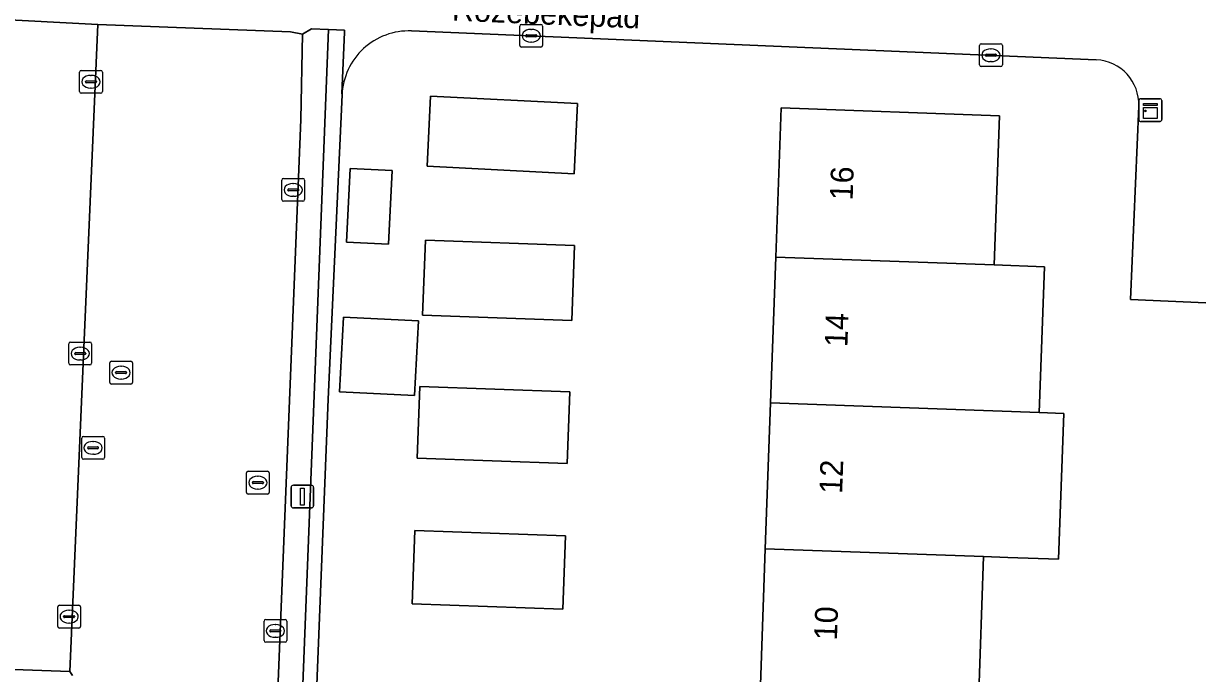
# Model space of a CAD drawing. Extents: x 160732 to 162107, y 387428 to 388479.
# Drawn here: x 161104.8 to 161156.4, y 387560.6 to 387589.1 of the extents above; entities that cross this region are included whole.
import ezdxf

# ---------------------------------------------------------------- set-up
doc = ezdxf.new("R2010")
doc.units = 0
for name, color, linetype in [('IMGEO_Brandkraan', 7, 'Continuous'), ('IMGEO_Erf', 7, 'Continuous'), ('IMGEO_Kast', 7, 'Continuous'), ('IMGEO_Kolk', 7, 'Continuous'), ('IMGEO_Lichtmast', 7, 'Continuous'), ('IMGEO_Openbare_ruimte_label', 7, 'Continuous'), ('IMGEO_Pand', 7, 'Continuous'), ('IMGEO_Pand_nummerreeks', 7, 'Continuous'), ('IMGEO_Parkeervlak_open', 7, 'Continuous'), ('IMGEO_Rijbaan_lokaal_open', 7, 'Continuous'), ('IMGEO_Rioolput', 7, 'Continuous'), ('IMGEO_Voetpad_open', 7, 'Continuous')]:
    doc.layers.add(name, color=color, linetype=linetype)

msp = doc.modelspace()

# ---------------------------------------------------------------- linework, layer by layer
at = {"layer": 'IMGEO_Brandkraan'}
for p, q in [((161114.587, 387568.537), (161114.587, 387569.389)), ((161114.662, 387569.463), (161115.514, 387569.463)), ((161115.075, 387569.243), (161115.1, 387569.243)), ((161115.588, 387569.389), (161115.588, 387568.537)), ((161114.846, 387568.957), (161114.846, 387568.969)), ((161115.284, 387568.92), (161114.886, 387568.92)), ((161114.889, 387569.006), (161115.287, 387569.006)), ((161115.098, 387568.683), (161115.073, 387568.683)), ((161115.33, 387568.969), (161115.33, 387568.957)), ((161115.514, 387568.463), (161114.662, 387568.463))]:
    msp.add_line(p, q, dxfattribs=at)
for points in [[(161114.587, 387568.537), (161114.587, 387569.389)], [(161114.662, 387569.463), (161115.514, 387569.463)], [(161115.588, 387569.389), (161115.588, 387568.537)], [(161115.514, 387568.463), (161114.662, 387568.463)]]:
    msp.add_lwpolyline(points, dxfattribs=at)
for centre, radius, start, end in [((161114.664, 387569.387), 0.0765, 91.552, 178.448), ((161114.664, 387569.387), 0.0765, 91.552, 178.448), ((161115.512, 387569.387), 0.0765, 1.552, 88.448), ((161115.512, 387569.387), 0.0765, 1.552, 88.448), ((161114.664, 387568.539), 0.0765, 181.552, 268.448), ((161114.664, 387568.539), 0.0765, 181.552, 268.448), ((161114.886, 387568.966), 0.0403, 85.8775, 175.7526), ((161114.883, 387568.956), 0.0366, 178.938, 274.7102), ((161115.287, 387568.963), 0.043, 264.8664, 352.4533), ((161115.291, 387568.968), 0.0386, 1.7309, 96.639), ((161115.512, 387568.539), 0.0765, 271.552, 358.448), ((161115.512, 387568.539), 0.0765, 271.552, 358.448)]:
    msp.add_arc(centre, radius, start, end, dxfattribs=at)
for centre, major_axis, ratio, start_param, end_param in [((161115.074, 387568.963), (-0.387, 0.002), 0.722429, 4.712389, 7.853982), ((161115.099, 387568.963), (-0.39, 0.002), 0.717154, 1.570796, 4.712389)]:
    msp.add_ellipse(centre, major_axis=major_axis, ratio=ratio, start_param=start_param, end_param=end_param, dxfattribs=at)
at = {"layer": 'IMGEO_Erf'}
for points in [[(161151.853, 387587.511), (161121.821, 387588.779)], [(161118.779, 387585.972), (161118.175, 387572.62), (161116.748, 387536.89)], [(161137.11, 387559.662), (161137.339, 387566.06), (161137.568, 387572.458), (161137.796, 387578.856), (161138.03, 387585.403), (161147.603, 387585.061), (161147.369, 387578.514), (161149.576, 387578.435), (161149.347, 387572.037), (161150.423, 387571.999), (161150.195, 387565.601), (161147.97, 387565.68), (161146.912, 387565.718), (161146.684, 387559.32)], [(161156.652, 387576.856), (161153.36, 387576.998), (161153.715, 387585.481)]]:
    msp.add_lwpolyline(points, dxfattribs=at)
for points in [[(161129.11, 387585.6), (161128.956, 387582.517), (161122.506, 387582.84), (161122.66, 387585.923)], [(161118.976, 387579.511), (161119.138, 387582.745), (161120.984, 387582.652), (161120.822, 387579.419)], [(161128.973, 387579.361), (161128.856, 387576.076), (161122.314, 387576.31), (161122.432, 387579.595)], [(161118.674, 387572.946), (161118.837, 387576.219), (161122.126, 387576.055), (161121.962, 387572.782)], [(161128.765, 387572.945), (161128.653, 387569.807), (161122.073, 387570.042), (161122.185, 387573.18)], [(161128.459, 387563.416), (161121.854, 387563.652), (161121.968, 387566.86), (161128.574, 387566.624)]]:
    msp.add_lwpolyline(points, close=True, dxfattribs=at)
for centre, radius, start, end in [((161121.702, 387585.856), 2.925, 87.6616, 177.7368), ((161151.767, 387585.563), 1.95, 357.5811, 87.4756)]:
    msp.add_arc(centre, radius, start, end, dxfattribs=at)
at = {"layer": 'IMGEO_Kast'}
for p, q in [((161153.724, 387584.883), (161153.724, 387585.724)), ((161153.724, 387585.724), (161153.724, 387584.883)), ((161153.799, 387585.808), (161154.64, 387585.808)), ((161154.64, 387585.808), (161153.799, 387585.808)), ((161154.724, 387585.733), (161154.724, 387584.892)), ((161154.724, 387584.892), (161154.724, 387585.733)), ((161154.649, 387584.808), (161153.808, 387584.808)), ((161153.808, 387584.808), (161154.649, 387584.808))]:
    msp.add_line(p, q, dxfattribs=at)
for points in [[(161153.919, 387585.598), (161154.519, 387585.598), (161154.519, 387585.513), (161153.919, 387585.513), (161153.919, 387585.598)], [(161153.919, 387585.423), (161154.519, 387585.423), (161154.519, 387584.934), (161153.919, 387584.934), (161153.919, 387585.423)]]:
    msp.add_lwpolyline(points, dxfattribs=at)
msp.add_circle((161154.003, 387585.272), 0.0377, dxfattribs=at)
for centre, start, end in [((161153.802, 387585.73), 92.4484, 184.2845), ((161153.802, 387585.73), 92.4484, 184.2845), ((161154.646, 387585.73), 2.4484, 94.2845), ((161154.646, 387585.73), 2.4484, 94.2845), ((161153.802, 387584.886), 182.4484, 274.2845), ((161153.802, 387584.886), 182.4484, 274.2845), ((161154.646, 387584.886), 272.4484, 4.2845), ((161154.646, 387584.886), 272.4484, 4.2845)]:
    msp.add_arc(centre, 0.0779, start, end, dxfattribs=at)
at = {"layer": 'IMGEO_Kolk'}
for p, q in [((161126.574, 387588.143), (161126.574, 387588.995)), ((161126.649, 387589.069), (161127.501, 387589.069)), ((161127.062, 387588.849), (161127.087, 387588.849)), ((161127.575, 387588.995), (161127.575, 387588.143)), ((161126.833, 387588.563), (161126.833, 387588.575)), ((161127.271, 387588.526), (161126.873, 387588.526)), ((161126.876, 387588.612), (161127.274, 387588.612)), ((161127.085, 387588.289), (161127.06, 387588.289)), ((161127.317, 387588.575), (161127.317, 387588.563)), ((161146.732, 387587.289), (161146.732, 387588.141)), ((161146.807, 387588.215), (161147.659, 387588.215)), ((161147.733, 387588.141), (161147.733, 387587.289)), ((161127.501, 387588.069), (161126.649, 387588.069)), ((161146.991, 387587.709), (161146.991, 387587.721)), ((161147.429, 387587.672), (161147.031, 387587.672)), ((161147.034, 387587.758), (161147.432, 387587.758)), ((161147.22, 387587.995), (161147.245, 387587.995)), ((161147.475, 387587.721), (161147.475, 387587.709)), ((161147.659, 387587.215), (161146.807, 387587.215)), ((161147.243, 387587.435), (161147.218, 387587.435)), ((161107.267, 387586.123), (161107.267, 387586.975)), ((161107.342, 387587.049), (161108.194, 387587.049)), ((161107.569, 387586.592), (161107.967, 387586.592)), ((161107.755, 387586.829), (161107.78, 387586.829)), ((161108.268, 387586.975), (161108.268, 387586.123)), ((161107.526, 387586.543), (161107.526, 387586.555)), ((161107.964, 387586.506), (161107.566, 387586.506)), ((161107.778, 387586.269), (161107.753, 387586.269)), ((161108.01, 387586.555), (161108.01, 387586.543)), ((161108.194, 387586.049), (161107.342, 387586.049)), ((161116.137, 387581.381), (161116.137, 387582.233)), ((161116.212, 387582.307), (161117.064, 387582.307)), ((161116.625, 387582.087), (161116.65, 387582.087)), ((161117.138, 387582.233), (161117.138, 387581.381)), ((161116.396, 387581.801), (161116.396, 387581.813)), ((161116.834, 387581.764), (161116.436, 387581.764)), ((161116.439, 387581.85), (161116.837, 387581.85)), ((161116.648, 387581.527), (161116.623, 387581.527)), ((161116.88, 387581.813), (161116.88, 387581.801)), ((161117.064, 387581.307), (161116.212, 387581.307)), ((161106.798, 387574.2), (161106.798, 387575.052)), ((161106.873, 387575.126), (161107.725, 387575.126)), ((161107.286, 387574.906), (161107.311, 387574.906)), ((161107.799, 387575.052), (161107.799, 387574.2)), ((161107.057, 387574.62), (161107.057, 387574.632)), ((161107.495, 387574.583), (161107.097, 387574.583)), ((161107.1, 387574.669), (161107.498, 387574.669)), ((161107.309, 387574.346), (161107.284, 387574.346)), ((161107.541, 387574.632), (161107.541, 387574.62)), ((161107.725, 387574.126), (161106.873, 387574.126)), ((161106.312, 387562.657), (161106.312, 387563.509)), ((161106.387, 387563.583), (161107.239, 387563.583)), ((161107.313, 387563.509), (161107.313, 387562.657)), ((161106.571, 387563.077), (161106.571, 387563.089)), ((161107.009, 387563.04), (161106.611, 387563.04)), ((161106.614, 387563.126), (161107.012, 387563.126)), ((161106.8, 387563.363), (161106.825, 387563.363)), ((161107.055, 387563.089), (161107.055, 387563.077)), ((161115.357, 387562.034), (161115.357, 387562.886)), ((161115.432, 387562.96), (161116.284, 387562.96)), ((161116.358, 387562.886), (161116.358, 387562.034)), ((161107.239, 387562.583), (161106.387, 387562.583)), ((161106.823, 387562.803), (161106.798, 387562.803)), ((161115.616, 387562.454), (161115.616, 387562.466)), ((161116.054, 387562.417), (161115.656, 387562.417)), ((161115.659, 387562.503), (161116.057, 387562.503)), ((161115.845, 387562.74), (161115.87, 387562.74)), ((161116.1, 387562.466), (161116.1, 387562.454)), ((161116.284, 387561.96), (161115.432, 387561.96)), ((161115.868, 387562.18), (161115.843, 387562.18))]:
    msp.add_line(p, q, dxfattribs=at)
for points in [[(161126.574, 387588.143), (161126.574, 387588.995)], [(161126.649, 387589.069), (161127.501, 387589.069)], [(161127.575, 387588.995), (161127.575, 387588.143)], [(161146.732, 387587.289), (161146.732, 387588.141)], [(161146.807, 387588.215), (161147.659, 387588.215)], [(161147.733, 387588.141), (161147.733, 387587.289)], [(161127.501, 387588.069), (161126.649, 387588.069)], [(161147.659, 387587.215), (161146.807, 387587.215)], [(161107.267, 387586.123), (161107.267, 387586.975)], [(161107.342, 387587.049), (161108.194, 387587.049)], [(161108.268, 387586.975), (161108.268, 387586.123)], [(161108.194, 387586.049), (161107.342, 387586.049)], [(161116.137, 387581.381), (161116.137, 387582.233)], [(161116.212, 387582.307), (161117.064, 387582.307)], [(161117.138, 387582.233), (161117.138, 387581.381)], [(161117.064, 387581.307), (161116.212, 387581.307)], [(161106.798, 387574.2), (161106.798, 387575.052)], [(161106.873, 387575.126), (161107.725, 387575.126)], [(161107.799, 387575.052), (161107.799, 387574.2)], [(161107.725, 387574.126), (161106.873, 387574.126)], [(161106.312, 387562.657), (161106.312, 387563.509)], [(161106.387, 387563.583), (161107.239, 387563.583)], [(161107.313, 387563.509), (161107.313, 387562.657)], [(161115.357, 387562.034), (161115.357, 387562.886)], [(161115.432, 387562.96), (161116.284, 387562.96)], [(161116.358, 387562.886), (161116.358, 387562.034)], [(161107.239, 387562.583), (161106.387, 387562.583)], [(161116.284, 387561.96), (161115.432, 387561.96)]]:
    msp.add_lwpolyline(points, dxfattribs=at)
for centre, radius, start, end in [((161126.651, 387588.993), 0.0765, 91.552, 178.448), ((161126.651, 387588.993), 0.0765, 91.552, 178.448), ((161127.499, 387588.993), 0.0765, 1.552, 88.448), ((161127.499, 387588.993), 0.0765, 1.552, 88.448), ((161126.651, 387588.145), 0.0765, 181.552, 268.448), ((161126.651, 387588.145), 0.0765, 181.552, 268.448), ((161126.873, 387588.572), 0.0403, 85.8775, 175.7526), ((161126.87, 387588.562), 0.0366, 178.938, 274.7102), ((161127.274, 387588.569), 0.043, 264.8664, 352.4533), ((161127.278, 387588.574), 0.0386, 1.7309, 96.639), ((161127.499, 387588.145), 0.0765, 271.552, 358.448), ((161127.499, 387588.145), 0.0765, 271.552, 358.448), ((161146.809, 387588.139), 0.0765, 91.552, 178.448), ((161146.809, 387588.139), 0.0765, 91.552, 178.448), ((161147.657, 387588.139), 0.0765, 1.552, 88.448), ((161147.657, 387588.139), 0.0765, 1.552, 88.448), ((161147.031, 387587.718), 0.0403, 85.8775, 175.7526), ((161147.028, 387587.708), 0.0366, 178.938, 274.7102), ((161147.432, 387587.715), 0.043, 264.8664, 352.4533), ((161147.436, 387587.72), 0.0386, 1.7309, 96.639), ((161146.809, 387587.291), 0.0765, 181.552, 268.448), ((161146.809, 387587.291), 0.0765, 181.552, 268.448), ((161147.657, 387587.291), 0.0765, 271.552, 358.448), ((161147.657, 387587.291), 0.0765, 271.552, 358.448), ((161107.344, 387586.973), 0.0765, 91.552, 178.448), ((161107.344, 387586.973), 0.0765, 91.552, 178.448), ((161107.566, 387586.552), 0.0403, 85.8775, 175.7526), ((161107.971, 387586.554), 0.0386, 1.7309, 96.639), ((161108.192, 387586.973), 0.0765, 1.552, 88.448), ((161108.192, 387586.973), 0.0765, 1.552, 88.448), ((161107.344, 387586.125), 0.0765, 181.552, 268.448), ((161107.344, 387586.125), 0.0765, 181.552, 268.448), ((161107.563, 387586.542), 0.0366, 178.938, 274.7102), ((161107.967, 387586.549), 0.043, 264.8664, 352.4533), ((161108.192, 387586.125), 0.0765, 271.552, 358.448), ((161108.192, 387586.125), 0.0765, 271.552, 358.448), ((161116.214, 387582.231), 0.0765, 91.552, 178.448), ((161116.214, 387582.231), 0.0765, 91.552, 178.448), ((161117.062, 387582.231), 0.0765, 1.552, 88.448), ((161117.062, 387582.231), 0.0765, 1.552, 88.448), ((161116.436, 387581.81), 0.0403, 85.8775, 175.7526), ((161116.433, 387581.8), 0.0366, 178.938, 274.7102), ((161116.837, 387581.807), 0.043, 264.8664, 352.4533), ((161116.841, 387581.812), 0.0386, 1.7309, 96.639), ((161116.214, 387581.383), 0.0765, 181.552, 268.448), ((161116.214, 387581.383), 0.0765, 181.552, 268.448), ((161117.062, 387581.383), 0.0765, 271.552, 358.448), ((161117.062, 387581.383), 0.0765, 271.552, 358.448), ((161106.875, 387575.05), 0.0765, 91.552, 178.448), ((161106.875, 387575.05), 0.0765, 91.552, 178.448), ((161107.723, 387575.05), 0.0765, 1.552, 88.448), ((161107.723, 387575.05), 0.0765, 1.552, 88.448), ((161106.875, 387574.202), 0.0765, 181.552, 268.448), ((161106.875, 387574.202), 0.0765, 181.552, 268.448), ((161107.097, 387574.629), 0.0403, 85.8775, 175.7526), ((161107.094, 387574.619), 0.0366, 178.938, 274.7102), ((161107.498, 387574.626), 0.043, 264.8664, 352.4533), ((161107.502, 387574.631), 0.0386, 1.7309, 96.639), ((161107.723, 387574.202), 0.0765, 271.552, 358.448), ((161107.723, 387574.202), 0.0765, 271.552, 358.448), ((161106.389, 387563.507), 0.0765, 91.552, 178.448), ((161106.389, 387563.507), 0.0765, 91.552, 178.448), ((161107.237, 387563.507), 0.0765, 1.552, 88.448), ((161107.237, 387563.507), 0.0765, 1.552, 88.448), ((161106.611, 387563.086), 0.0403, 85.8775, 175.7526), ((161106.608, 387563.076), 0.0366, 178.938, 274.7102), ((161107.012, 387563.083), 0.043, 264.8664, 352.4533), ((161107.016, 387563.088), 0.0386, 1.7309, 96.639), ((161115.434, 387562.884), 0.0765, 91.552, 178.448), ((161115.434, 387562.884), 0.0765, 91.552, 178.448), ((161116.282, 387562.884), 0.0765, 1.552, 88.448), ((161116.282, 387562.884), 0.0765, 1.552, 88.448), ((161106.389, 387562.659), 0.0765, 181.552, 268.448), ((161106.389, 387562.659), 0.0765, 181.552, 268.448), ((161107.237, 387562.659), 0.0765, 271.552, 358.448), ((161107.237, 387562.659), 0.0765, 271.552, 358.448), ((161115.656, 387562.463), 0.0403, 85.8775, 175.7526), ((161115.653, 387562.453), 0.0366, 178.938, 274.7102), ((161116.057, 387562.46), 0.043, 264.8664, 352.4533), ((161116.061, 387562.465), 0.0386, 1.7309, 96.639), ((161115.434, 387562.036), 0.0765, 181.552, 268.448), ((161115.434, 387562.036), 0.0765, 181.552, 268.448), ((161116.282, 387562.036), 0.0765, 271.552, 358.448), ((161116.282, 387562.036), 0.0765, 271.552, 358.448)]:
    msp.add_arc(centre, radius, start, end, dxfattribs=at)
for centre, major_axis, ratio, start_param, end_param in [((161127.061, 387588.569), (-0.387, 0.002), 0.722429, 4.712389, 7.853982), ((161127.086, 387588.569), (-0.39, 0.002), 0.717154, 1.570796, 4.712389), ((161147.219, 387587.715), (-0.387, 0.002), 0.722429, 4.712389, 7.853982), ((161147.244, 387587.715), (-0.39, 0.002), 0.717154, 1.570796, 4.712389), ((161107.754, 387586.549), (-0.387, 0.002), 0.722429, 4.712389, 7.853982), ((161107.779, 387586.549), (-0.39, 0.002), 0.717154, 1.570796, 4.712389), ((161116.624, 387581.807), (-0.387, 0.002), 0.722429, 4.712389, 7.853982), ((161116.649, 387581.807), (-0.39, 0.002), 0.717154, 1.570796, 4.712389), ((161107.285, 387574.626), (-0.387, 0.002), 0.722429, 4.712389, 7.853982), ((161107.31, 387574.626), (-0.39, 0.002), 0.717154, 1.570796, 4.712389), ((161106.799, 387563.083), (-0.387, 0.002), 0.722429, 4.712389, 7.853982), ((161106.824, 387563.083), (-0.39, 0.002), 0.717154, 1.570796, 4.712389), ((161115.844, 387562.46), (-0.387, 0.002), 0.722429, 4.712389, 7.853982), ((161115.869, 387562.46), (-0.39, 0.002), 0.717154, 1.570796, 4.712389)]:
    msp.add_ellipse(centre, major_axis=major_axis, ratio=ratio, start_param=start_param, end_param=end_param, dxfattribs=at)
at = {"layer": 'IMGEO_Lichtmast'}
for p, q in [((161116.544, 387567.952), (161116.544, 387568.752)), ((161116.544, 387568.752), (161116.544, 387567.952)), ((161116.644, 387568.852), (161117.434, 387568.852)), ((161117.434, 387568.852), (161116.644, 387568.852)), ((161117.534, 387568.752), (161117.534, 387567.952)), ((161117.534, 387567.952), (161117.534, 387568.752)), ((161117.434, 387567.852), (161116.644, 387567.852)), ((161116.644, 387567.852), (161117.434, 387567.852))]:
    msp.add_line(p, q, dxfattribs=at)
msp.add_lwpolyline([(161116.964, 387568.727), (161117.114, 387568.727), (161117.114, 387567.977), (161116.964, 387567.977), (161116.964, 387568.727)], dxfattribs=at)
for centre, start, end in [((161116.644, 387568.752), 90, 180), ((161116.644, 387568.752), 90, 180), ((161117.434, 387568.752), 0, 90), ((161117.434, 387568.752), 360, 90), ((161116.644, 387567.952), 180, 270), ((161116.644, 387567.952), 180, 270), ((161117.434, 387567.952), 270, 0), ((161117.434, 387567.952), 270, 0)]:
    msp.add_arc(centre, 0.1, start, end, dxfattribs=at)
at = {"layer": 'IMGEO_Pand'}
for points in [[(161129.11, 387585.6), (161122.66, 387585.923), (161122.506, 387582.84), (161128.956, 387582.517)], [(161147.369, 387578.514), (161147.603, 387585.061), (161138.03, 387585.403), (161137.796, 387578.856)], [(161118.976, 387579.511), (161120.822, 387579.419), (161120.984, 387582.652), (161119.138, 387582.745)], [(161128.973, 387579.361), (161122.432, 387579.595), (161122.314, 387576.31), (161128.856, 387576.076)], [(161147.369, 387578.514), (161137.796, 387578.856), (161137.568, 387572.458), (161149.347, 387572.037), (161149.576, 387578.435)], [(161118.674, 387572.946), (161121.962, 387572.782), (161122.126, 387576.055), (161118.837, 387576.219)], [(161128.765, 387572.945), (161122.185, 387573.18), (161122.073, 387570.042), (161128.653, 387569.807)], [(161147.97, 387565.68), (161150.195, 387565.601), (161150.423, 387571.999), (161149.347, 387572.037), (161137.568, 387572.458), (161137.339, 387566.06), (161146.912, 387565.718)], [(161128.574, 387566.624), (161121.968, 387566.86), (161121.854, 387563.652), (161128.459, 387563.416)], [(161137.339, 387566.06), (161137.11, 387559.662), (161146.684, 387559.32), (161146.912, 387565.718)]]:
    msp.add_lwpolyline(points, close=True, dxfattribs=at)
at = {"layer": 'IMGEO_Parkeervlak_open'}
msp.add_lwpolyline([(161108.069, 387589.065), (161103.346, 387589.308), (161103.191, 387589.194), (161103.114, 387589.006), (161101.914, 387560.852), (161106.849, 387560.672)], close=True, dxfattribs=at)
at = {"layer": 'IMGEO_Rijbaan_lokaal_open'}
msp.add_lwpolyline([(161115.055, 387537.387), (161116.968, 387584.894), (161117.052, 387588.641), (161116.513, 387588.747), (161108.069, 387589.065), (161106.849, 387560.672), (161106.955, 387560.508)], dxfattribs=at)
at = {"layer": 'IMGEO_Rioolput'}
for p, q in [((161108.591, 387573.363), (161108.591, 387574.215)), ((161108.666, 387574.289), (161109.518, 387574.289)), ((161109.592, 387574.215), (161109.592, 387573.363)), ((161108.85, 387573.783), (161108.85, 387573.795)), ((161109.288, 387573.746), (161108.89, 387573.746)), ((161108.893, 387573.832), (161109.291, 387573.832)), ((161109.079, 387574.069), (161109.104, 387574.069)), ((161109.334, 387573.795), (161109.334, 387573.783)), ((161109.518, 387573.289), (161108.666, 387573.289)), ((161109.102, 387573.509), (161109.077, 387573.509)), ((161107.363, 387570.063), (161107.363, 387570.915)), ((161107.438, 387570.989), (161108.29, 387570.989)), ((161107.851, 387570.769), (161107.876, 387570.769)), ((161108.364, 387570.915), (161108.364, 387570.063)), ((161107.622, 387570.483), (161107.622, 387570.495)), ((161108.06, 387570.446), (161107.662, 387570.446)), ((161107.665, 387570.532), (161108.063, 387570.532)), ((161107.874, 387570.209), (161107.849, 387570.209)), ((161108.106, 387570.495), (161108.106, 387570.483)), ((161108.29, 387569.989), (161107.438, 387569.989))]:
    msp.add_line(p, q, dxfattribs=at)
for points in [[(161108.591, 387573.363), (161108.591, 387574.215)], [(161108.666, 387574.289), (161109.518, 387574.289)], [(161109.592, 387574.215), (161109.592, 387573.363)], [(161109.518, 387573.289), (161108.666, 387573.289)], [(161107.363, 387570.063), (161107.363, 387570.915)], [(161107.438, 387570.989), (161108.29, 387570.989)], [(161108.364, 387570.915), (161108.364, 387570.063)], [(161108.29, 387569.989), (161107.438, 387569.989)]]:
    msp.add_lwpolyline(points, dxfattribs=at)
for centre, radius, start, end in [((161108.668, 387574.213), 0.0765, 91.552, 178.448), ((161108.668, 387574.213), 0.0765, 91.552, 178.448), ((161109.516, 387574.213), 0.0765, 1.552, 88.448), ((161109.516, 387574.213), 0.0765, 1.552, 88.448), ((161108.89, 387573.792), 0.0403, 85.8775, 175.7526), ((161108.887, 387573.782), 0.0366, 178.938, 274.7102), ((161109.291, 387573.789), 0.043, 264.8664, 352.4533), ((161109.295, 387573.794), 0.0386, 1.7309, 96.639), ((161108.668, 387573.365), 0.0765, 181.552, 268.448), ((161108.668, 387573.365), 0.0765, 181.552, 268.448), ((161109.516, 387573.365), 0.0765, 271.552, 358.448), ((161109.516, 387573.365), 0.0765, 271.552, 358.448), ((161107.44, 387570.913), 0.0765, 91.552, 178.448), ((161107.44, 387570.913), 0.0765, 91.552, 178.448), ((161108.288, 387570.913), 0.0765, 1.552, 88.448), ((161108.288, 387570.913), 0.0765, 1.552, 88.448), ((161107.662, 387570.492), 0.0403, 85.8775, 175.7526), ((161107.659, 387570.482), 0.0366, 178.938, 274.7102), ((161108.063, 387570.489), 0.043, 264.8664, 352.4533), ((161108.067, 387570.494), 0.0386, 1.7309, 96.639), ((161107.44, 387570.065), 0.0765, 181.552, 268.448), ((161107.44, 387570.065), 0.0765, 181.552, 268.448), ((161108.288, 387570.065), 0.0765, 271.552, 358.448), ((161108.288, 387570.065), 0.0765, 271.552, 358.448)]:
    msp.add_arc(centre, radius, start, end, dxfattribs=at)
for centre, major_axis, ratio, start_param, end_param in [((161109.078, 387573.789), (-0.387, 0.002), 0.722429, 4.712389, 7.853982), ((161109.103, 387573.789), (-0.39, 0.002), 0.717154, 1.570796, 4.712389), ((161107.85, 387570.489), (-0.387, 0.002), 0.722429, 4.712389, 7.853982), ((161107.875, 387570.489), (-0.39, 0.002), 0.717154, 1.570796, 4.712389)]:
    msp.add_ellipse(centre, major_axis=major_axis, ratio=ratio, start_param=start_param, end_param=end_param, dxfattribs=at)
at = {"layer": 'IMGEO_Voetpad_open'}
for points in [[(161101.25, 387593.987), (161101.084, 387589.83), (161101.074, 387589.627), (161102.026, 387589.6), (161102.943, 387589.574), (161103.191, 387589.194), (161103.346, 387589.308), (161108.069, 387589.065), (161116.513, 387588.747), (161117.052, 387588.641), (161117.438, 387588.871), (161118.188, 387588.85), (161118.883, 387588.815), (161118.88, 387588.732), (161118.777, 387586.033), (161118.779, 387585.972)], [(161106.955, 387560.508), (161106.849, 387560.672), (161101.914, 387560.852), (161100.842, 387560.883), (161102.026, 387589.6)], [(161118.779, 387585.972), (161118.777, 387586.033), (161118.88, 387588.732), (161118.883, 387588.815), (161118.188, 387588.85), (161116.164, 387537.336), (161115.055, 387537.387)], [(161121.821, 387588.779), (161151.853, 387587.511)], [(161160.169, 387532.563), (161154.919, 387533.12), (161148.873, 387533.469), (161136.191, 387533.922), (161136.177, 387533.542), (161131.639, 387533.72), (161118.993, 387534.338), (161116.748, 387536.89), (161118.175, 387572.62), (161118.779, 387585.972)], [(161153.715, 387585.481), (161153.36, 387576.998), (161156.652, 387576.856)]]:
    msp.add_lwpolyline(points, dxfattribs=at)
msp.add_lwpolyline([(161116.164, 387537.336), (161118.188, 387588.85), (161117.438, 387588.871), (161117.052, 387588.641), (161116.968, 387584.894), (161115.055, 387537.387)], close=True, dxfattribs=at)
for centre, radius, start, end in [((161121.702, 387585.856), 2.925, 87.6616, 177.7368), ((161151.767, 387585.563), 1.95, 357.5811, 87.4756)]:
    msp.add_arc(centre, radius, start, end, dxfattribs=at)

# ---------------------------------------------------------------- texts
at = {"layer": 'IMGEO_Openbare_ruimte_label'}
msp.add_text('Rozebekepad', height=1, rotation=357.5926, dxfattribs=at).set_placement((161123.588, 387589.235))
at = {"layer": 'IMGEO_Pand_nummerreeks'}
for s, p in [('16', (161141.167, 387581.334)), ('14', (161140.937, 387574.899)), ('12', (161140.707, 387568.461)), ('10', (161140.478, 387562.032))]:
    msp.add_text(s, height=1, rotation=87.9542, dxfattribs=at).set_placement(p)

doc.saveas('drawing.dxf')
